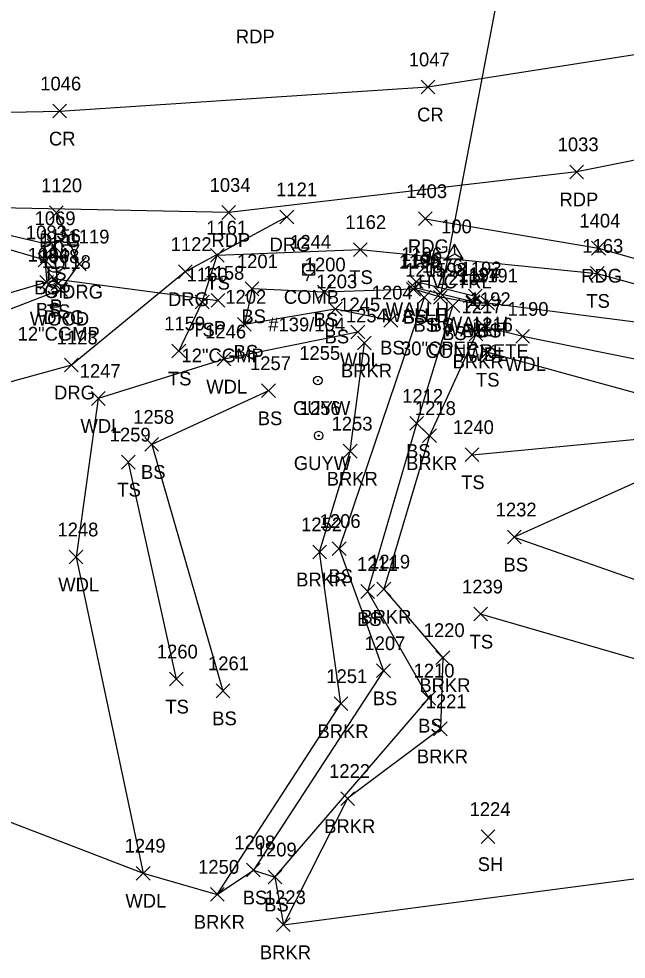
# Model space of a CAD drawing. Extents: x 1633660 to 1636532, y 388643 to 392631.
# Drawn here: x 1633906 to 1633994.3, y 388645.9 to 388782.5 of the extents above; entities that cross this region are included whole.
import ezdxf

# ---------------------------------------------------------------- set-up
doc = ezdxf.new("R2010")
doc.units = 0
for name, color, linetype in [('C_A', 7, 'Continuous'), ('C_I', 7, 'Continuous'), ('CPSM', 7, 'Continuous'), ('D_A', 7, 'Continuous'), ('D_C', 7, 'Continuous'), ('D_I', 7, 'Continuous'), ('D_TIC', 7, 'Continuous'), ('DCP', 7, 'Continuous'), ('DHW', 7, 'Continuous'), ('L_A', 7, 'Continuous'), ('L_I', 7, 'Continuous'), ('L_TIC', 7, 'Continuous'), ('LAWA', 7, 'Continuous'), ('LAWE', 7, 'Continuous'), ('LELB', 7, 'Continuous'), ('LSOGP', 7, 'Continuous'), ('P_A', 7, 'Continuous'), ('P_I', 7, 'Continuous'), ('P_TIC', 7, 'Continuous'), ('PET', 7, 'Continuous'), ('PEU', 7, 'Continuous'), ('PRC', 7, 'Continuous'), ('R_A', 7, 'Continuous'), ('R_C', 7, 'Continuous'), ('R_I', 7, 'Continuous'), ('R_TIC', 7, 'Continuous'), ('RDG', 7, 'Continuous'), ('RGP', 7, 'Continuous'), ('U_A', 7, 'Continuous'), ('U_C', 7, 'Continuous'), ('U_I', 7, 'Continuous'), ('UP', 7, 'Continuous'), ('UPGW', 7, 'Continuous')]:
    doc.layers.add(name, color=color, linetype=linetype)

msp = doc.modelspace()

# ---------------------------------------------------------------- linework, layer by layer
at = {"layer": 'CPSM'}
for p, q in [((1633968.08, 388747.6), (1633969.33, 388749.76)), ((1633970.58, 388747.6), (1633969.33, 388749.76)), ((1633969.34, 388748.32), (1633969.33, 388749.76)), ((1633968.08, 388747.6), (1633969.34, 388748.32)), ((1633969.34, 388748.32), (1633969.34, 388748.32)), ((1633969.34, 388748.32), (1633970.58, 388747.6)), ((1633968.08, 388747.6), (1633970.58, 388747.6))]:
    msp.add_line(p, q, dxfattribs=at)
at = {"layer": 'D_TIC'}
for points in [[(1633910.11, 388743.73), (1633912.11, 388745.73)], [(1633912.11, 388743.73), (1633910.11, 388745.73)], [(1633962.74, 388743.3), (1633964.74, 388745.3)], [(1633964.74, 388743.3), (1633962.74, 388745.3)], [(1633962.54, 388742.42), (1633964.54, 388744.42)], [(1633964.54, 388742.42), (1633962.54, 388744.42)], [(1633933.93, 388740.58), (1633935.93, 388742.58)], [(1633935.93, 388740.58), (1633933.93, 388742.58)], [(1633966.31, 388741.59), (1633968.31, 388743.59)], [(1633968.31, 388741.59), (1633966.31, 388743.59)], [(1633971, 388740.37), (1633973, 388742.37)], [(1633973, 388740.37), (1633971, 388742.37)], [(1633971.33, 388741.21), (1633973.33, 388743.21)], [(1633973.33, 388741.21), (1633971.33, 388743.21)]]:
    msp.add_lwpolyline(points, dxfattribs=at)
at = {"layer": 'DCP'}
for points in [[(1633978.41, 388800.74), (1633967.31, 388742.59)], [(1633911.11, 388744.73), (1633934.93, 388741.58)]]:
    msp.add_lwpolyline(points, dxfattribs=at)
at = {"layer": 'DHW'}
for points in [[(1633972.33, 388742.21), (1633972, 388741.37), (1633963.54, 388743.42), (1633963.74, 388744.3)], [(1633963.74, 388744.3), (1633972.33, 388742.21)]]:
    msp.add_lwpolyline(points, dxfattribs=at)
at = {"layer": 'L_TIC'}
for points in [[(1633910.1, 388748.51), (1633912.1, 388750.51)], [(1633912.1, 388748.51), (1633910.1, 388750.51)], [(1633954.61, 388747.95), (1633956.61, 388749.95)], [(1633956.61, 388747.95), (1633954.61, 388749.95)], [(1633908.78, 388746.45), (1633910.78, 388748.45)], [(1633910.78, 388746.45), (1633908.78, 388748.45)], [(1633933.84, 388747.14), (1633935.84, 388749.14)], [(1633935.84, 388747.14), (1633933.84, 388749.14)], [(1633989.07, 388744.5), (1633991.07, 388746.5)], [(1633991.07, 388744.5), (1633989.07, 388746.5)], [(1633909.04, 388743.21), (1633911.04, 388745.21)], [(1633911.04, 388743.21), (1633909.04, 388745.21)], [(1633910.66, 388743), (1633912.66, 388745)], [(1633912.66, 388743), (1633910.66, 388745)], [(1633938.89, 388742.26), (1633940.89, 388744.26)], [(1633940.89, 388742.26), (1633938.89, 388744.26)], [(1633949.4, 388741.79), (1633951.4, 388743.79)], [(1633951.4, 388741.79), (1633949.4, 388743.79)], [(1633962.35, 388742.2), (1633964.35, 388744.2)], [(1633964.35, 388742.2), (1633962.35, 388744.2)], [(1633963.91, 388741.02), (1633965.91, 388743.02)], [(1633965.91, 388741.02), (1633963.91, 388743.02)], [(1633966.26, 388741.03), (1633968.26, 388743.03)], [(1633968.26, 388741.03), (1633966.26, 388743.03)], [(1633931.64, 388740.33), (1633933.64, 388742.33)], [(1633933.64, 388740.33), (1633931.64, 388742.33)], [(1633950.99, 388739.33), (1633952.99, 388741.33)], [(1633952.99, 388739.33), (1633950.99, 388741.33)], [(1633968.07, 388739.81), (1633970.07, 388741.81)], [(1633970.07, 388739.81), (1633968.07, 388741.81)], [(1633970.98, 388740.19), (1633972.98, 388742.19)], [(1633972.98, 388740.19), (1633970.98, 388742.19)], [(1633973.13, 388740.19), (1633975.13, 388742.19)], [(1633975.13, 388740.19), (1633973.13, 388742.19)], [(1633959.06, 388737.71), (1633961.06, 388739.71)], [(1633961.06, 388737.71), (1633959.06, 388739.71)], [(1633937.77, 388737.1), (1633939.77, 388739.1)], [(1633939.77, 388737.1), (1633937.77, 388739.1)], [(1633972.65, 388736.75), (1633974.65, 388738.75)], [(1633974.65, 388736.75), (1633972.65, 388738.75)], [(1633954.26, 388735.98), (1633956.26, 388737.98)], [(1633956.26, 388735.98), (1633954.26, 388737.98)], [(1633971.45, 388735.7), (1633973.45, 388737.7)], [(1633973.45, 388735.7), (1633971.45, 388737.7)], [(1633978.24, 388735.34), (1633980.24, 388737.34)], [(1633980.24, 388735.34), (1633978.24, 388737.34)], [(1633955.22, 388734.38), (1633957.22, 388736.38)], [(1633957.22, 388734.38), (1633955.22, 388736.38)], [(1633928.25, 388733.22), (1633930.25, 388735.22)], [(1633930.25, 388733.22), (1633928.25, 388735.22)], [(1633973.03, 388733.05), (1633975.03, 388735.05)], [(1633975.03, 388733.05), (1633973.03, 388735.05)], [(1633934.82, 388732.05), (1633936.82, 388734.05)], [(1633936.82, 388732.05), (1633934.82, 388734.05)], [(1633941.28, 388727.45), (1633943.28, 388729.45)], [(1633943.28, 388727.45), (1633941.28, 388729.45)], [(1633916.53, 388726.33), (1633918.53, 388728.33)], [(1633918.53, 388726.33), (1633916.53, 388728.33)], [(1633962.83, 388722.7), (1633964.83, 388724.7)], [(1633964.83, 388722.7), (1633962.83, 388724.7)], [(1633964.68, 388720.92), (1633966.68, 388722.92)], [(1633966.68, 388720.92), (1633964.68, 388722.92)], [(1633924.3, 388719.65), (1633926.3, 388721.65)], [(1633926.3, 388719.65), (1633924.3, 388721.65)], [(1633953.15, 388718.67), (1633955.15, 388720.67)], [(1633955.15, 388718.67), (1633953.15, 388720.67)], [(1633970.87, 388718.16), (1633972.87, 388720.16)], [(1633972.87, 388718.16), (1633970.87, 388720.16)], [(1633920.9, 388717.08), (1633922.9, 388719.08)], [(1633922.9, 388717.08), (1633920.9, 388719.08)], [(1633977, 388706.19), (1633979, 388708.19)], [(1633979, 388706.19), (1633977, 388708.19)], [(1633948.71, 388704.03), (1633950.71, 388706.03)], [(1633950.71, 388704.03), (1633948.71, 388706.03)], [(1633951.55, 388704.52), (1633953.55, 388706.52)], [(1633953.55, 388704.52), (1633951.55, 388706.52)], [(1633913.3, 388703.29), (1633915.3, 388705.29)], [(1633915.3, 388703.29), (1633913.3, 388705.29)], [(1633955.71, 388698.28), (1633957.71, 388700.28)], [(1633957.71, 388698.28), (1633955.71, 388700.28)], [(1633958.04, 388698.62), (1633960.04, 388700.62)], [(1633960.04, 388698.62), (1633958.04, 388700.62)], [(1633972.11, 388695), (1633974.11, 388697)], [(1633974.11, 388695), (1633972.11, 388697)], [(1633966.62, 388688.67), (1633968.62, 388690.67)], [(1633968.62, 388688.67), (1633966.62, 388690.67)], [(1633958, 388686.77), (1633960, 388688.77)], [(1633960, 388686.77), (1633958, 388688.77)], [(1633927.88, 388685.56), (1633929.88, 388687.56)], [(1633929.88, 388685.56), (1633927.88, 388687.56)], [(1633934.66, 388683.85), (1633936.66, 388685.85)], [(1633936.66, 388683.85), (1633934.66, 388685.85)], [(1633951.81, 388681.98), (1633953.81, 388683.98)], [(1633953.81, 388681.98), (1633951.81, 388683.98)], [(1633964.59, 388682.79), (1633966.59, 388684.79)], [(1633966.59, 388682.79), (1633964.59, 388684.79)], [(1633966.26, 388678.33), (1633968.26, 388680.33)], [(1633968.26, 388678.33), (1633966.26, 388680.33)], [(1633952.78, 388668.2), (1633954.78, 388670.2)], [(1633954.78, 388668.2), (1633952.78, 388670.2)], [(1633973.2, 388662.67), (1633975.2, 388664.67)], [(1633975.2, 388662.67), (1633973.2, 388664.67)], [(1633923.06, 388657.35), (1633925.06, 388659.35)], [(1633925.06, 388657.35), (1633923.06, 388659.35)], [(1633939.09, 388657.82), (1633941.09, 388659.82)], [(1633941.09, 388657.82), (1633939.09, 388659.82)], [(1633942.21, 388656.8), (1633944.21, 388658.8)], [(1633944.21, 388656.8), (1633942.21, 388658.8)], [(1633933.83, 388654.28), (1633935.83, 388656.28)], [(1633935.83, 388654.28), (1633933.83, 388656.28)], [(1633943.44, 388649.87), (1633945.44, 388651.87)], [(1633945.44, 388649.87), (1633943.44, 388651.87)]]:
    msp.add_lwpolyline(points, dxfattribs=at)
at = {"layer": 'LAWA'}
for points in [[(1633955.26, 388736.98), (1633935.82, 388733.05), (1633917.53, 388727.33), (1633914.3, 388704.29), (1633924.06, 388658.35)], [(1634213.54, 388715.93), (1634181.29, 388718.06), (1634158.57, 388709.96), (1634132.08, 388702.35), (1634126.3, 388716.32), (1634107.18, 388718.38), (1634087.11, 388719.77), (1634044.14, 388728.03), (1634007.74, 388730.58), (1633979.24, 388736.34), (1633973.65, 388737.75)]]:
    msp.add_lwpolyline(points, dxfattribs=at)
at = {"layer": 'LAWE'}
for points in [[(1633972.45, 388736.7), (1633965.68, 388721.92), (1633959.04, 388699.62), (1633967.62, 388689.67), (1633967.26, 388679.33), (1633953.78, 388669.2), (1633944.44, 388650.87)], [(1633934.83, 388655.28), (1633952.81, 388682.98), (1633949.71, 388705.03), (1633954.15, 388719.67), (1633956.22, 388735.38)]]:
    msp.add_lwpolyline(points, dxfattribs=at)
at = {"layer": 'LELB'}
for points in [[(1633911.66, 388744), (1633911.1, 388749.51), (1633895.3, 388753.2), (1633839.2, 388752.39), (1633786.72, 388748.73), (1633746.63, 388742.98), (1633714.32, 388735.32), (1633689.52, 388727.84)], [(1633690.14, 388726.28), (1633715.09, 388734.26), (1633748.91, 388740.99), (1633779.57, 388746.6), (1633826.21, 388749.36), (1633872.99, 388751.1), (1633902.8, 388749.5), (1633909.78, 388747.45), (1633910.04, 388744.21), (1633875.63, 388734.16), (1633829.55, 388729.69), (1633792.31, 388730.74), (1633761.73, 388730.77), (1633732.76, 388723.1), (1633695, 388705.89)], [(1633929.25, 388734.22), (1633932.64, 388741.33), (1633934.84, 388748.14), (1633955.61, 388748.95), (1633990.07, 388745.5), (1634019.59, 388737.41), (1634056.05, 388731.14), (1634102.32, 388725.85), (1634131.53, 388723.22), (1634169.63, 388722.22), (1634213.51, 388722.74)], [(1634103.78, 388721.69), (1634089.59, 388723.27), (1634044.5, 388730.63), (1634008.78, 388736.74), (1633974.13, 388741.19), (1633971.98, 388741.19), (1633967.26, 388742.03), (1633963.35, 388743.2), (1633950.4, 388742.79), (1633939.89, 388743.26), (1633938.77, 388738.1), (1633951.99, 388740.33), (1633960.06, 388738.71)], [(1633964.91, 388742.02), (1633952.55, 388705.52), (1633959, 388687.77), (1633940.09, 388658.82)], [(1633943.21, 388657.8), (1633965.59, 388683.79), (1633956.71, 388699.28), (1633963.83, 388723.7), (1633969.07, 388740.81)], [(1634025.68, 388725.69), (1633998.33, 388727.39), (1633974.03, 388734.05)], [(1633942.28, 388728.45), (1633925.3, 388720.65), (1633935.66, 388684.85)], [(1634027.27, 388723.64), (1634003.26, 388718.58), (1633978, 388707.19), (1634015.59, 388694.03), (1634040.67, 388699.59), (1634065.09, 388695.5)], [(1633971.87, 388719.16), (1633998.85, 388721.73)], [(1633921.9, 388718.08), (1633928.88, 388686.56)], [(1634057.83, 388688.85), (1634031.65, 388692.09), (1634009.4, 388685.46), (1633973.11, 388696)]]:
    msp.add_lwpolyline(points, dxfattribs=at)
at = {"layer": 'LSOGP'}
msp.add_lwpolyline([(1633892.15, 388670.64), (1633924.06, 388658.35), (1633934.83, 388655.28), (1633940.09, 388658.82), (1633943.21, 388657.8), (1633944.44, 388650.87), (1634007.22, 388659.11), (1634047.38, 388665.25), (1634068.61, 388685.27), (1634091.13, 388687.87), (1634119.65, 388686.04), (1634149.89, 388685.18), (1634208.91, 388690.49), (1634214.85, 388708.43), (1634213.54, 388715.93), (1634213.47, 388720.91), (1634213.51, 388722.74), (1634213.85, 388724.5), (1634214.78, 388736.17), (1634218.98, 388740.85), (1634254.67, 388740.24)], dxfattribs=at)
at = {"layer": 'P_TIC'}
for points in [[(1633964.45, 388771.58), (1633966.45, 388773.58)], [(1633966.45, 388771.58), (1633964.45, 388773.58)], [(1633910.93, 388768.08), (1633912.93, 388770.08)], [(1633912.93, 388768.08), (1633910.93, 388770.08)], [(1633986.08, 388759.24), (1633988.08, 388761.24)], [(1633988.08, 388759.24), (1633986.08, 388761.24)], [(1633935.49, 388753.34), (1633937.49, 388755.34)], [(1633937.49, 388753.34), (1633935.49, 388755.34)], [(1633964.07, 388752.44), (1633966.07, 388754.44)], [(1633966.07, 388752.44), (1633964.07, 388754.44)], [(1633989.25, 388748.16), (1633991.25, 388750.16)], [(1633991.25, 388748.16), (1633989.25, 388750.16)]]:
    msp.add_lwpolyline(points, dxfattribs=at)
at = {"layer": 'PET'}
msp.add_lwpolyline([(1634233.66, 388838.29), (1634176.14, 388816.11), (1634127.42, 388797.4), (1634083.73, 388783.04), (1634035.91, 388770.06), (1633987.08, 388760.24), (1633936.49, 388754.34), (1633886.38, 388755.37), (1633827.16, 388754.09), (1633779.6, 388750.43), (1633734.35, 388742.35), (1633709.35, 388735.6), (1633689.74, 388728.83)], dxfattribs=at)
at = {"layer": 'PEU'}
msp.add_lwpolyline([(1633965.07, 388753.44), (1633990.25, 388749.16), (1634020.6, 388740.58), (1634057, 388733.24), (1634101.12, 388727.81), (1634139.19, 388724.39), (1634181.63, 388724.18), (1634213.85, 388724.5)], dxfattribs=at)
at = {"layer": 'PRC'}
msp.add_lwpolyline([(1633685.21, 388740.89), (1633722.47, 388753.09), (1633765.95, 388761.74), (1633808.84, 388766.45), (1633860.63, 388768.05), (1633911.93, 388769.08), (1633965.45, 388772.58), (1634019.68, 388781.06), (1634071.37, 388793.87), (1634111.14, 388806.36), (1634160.92, 388824.06), (1634207.93, 388842.02), (1634253.71, 388860.36), (1634302.74, 388880.25), (1634347.86, 388899.14), (1634390.05, 388916.89), (1634425.6, 388933.8), (1634443.27, 388943.77), (1634464.46, 388957.57)], dxfattribs=at)
at = {"layer": 'R_TIC'}
for points in [[(1633910.44, 388753.3), (1633912.44, 388755.3)], [(1633912.44, 388753.3), (1633910.44, 388755.3)], [(1633943.95, 388752.7), (1633945.95, 388754.7)], [(1633945.95, 388752.7), (1633943.95, 388754.7)], [(1633913.78, 388745.85), (1633915.78, 388747.85)], [(1633915.78, 388745.85), (1633913.78, 388747.85)], [(1633929.18, 388744.75), (1633931.18, 388746.75)], [(1633931.18, 388744.75), (1633929.18, 388746.75)], [(1633911.07, 388742.14), (1633913.07, 388744.14)], [(1633913.07, 388742.14), (1633911.07, 388744.14)], [(1633912.62, 388731.19), (1633914.62, 388733.19)], [(1633914.62, 388731.19), (1633912.62, 388733.19)]]:
    msp.add_lwpolyline(points, dxfattribs=at)
at = {"layer": 'RDG'}
for points in [[(1633696.84, 388696.34), (1633718.61, 388710.13), (1633753.19, 388721.71), (1633815.96, 388725.01), (1633854.78, 388728.2), (1633888.67, 388734.15), (1633912.07, 388743.14), (1633914.78, 388746.85), (1633911.44, 388754.3)], [(1633944.95, 388753.7), (1633930.18, 388745.75), (1633913.62, 388732.19), (1633871.15, 388720.48), (1633820.72, 388716.51), (1633780.18, 388714.86), (1633742.93, 388709.56), (1633718.39, 388700.15), (1633699.77, 388685.7)]]:
    msp.add_lwpolyline(points, dxfattribs=at)
at = {"layer": 'RGP'}
msp.add_line((1633911.24, 388746.92), (1633911.24, 388746.92), dxfattribs=at)
for radius in [1.25, 0.0833]:
    msp.add_circle((1633911.24, 388746.92), radius, dxfattribs=at)
at = {"layer": 'UP'}
for p, q in [((1633947.29, 388745.24), (1633947.29, 388746.91)), ((1633947.29, 388746.91), (1633948.95, 388746.91)), ((1633948.37, 388747.74), (1633948.12, 388746.91)), ((1633948.95, 388746.91), (1633948.95, 388745.24)), ((1633948.95, 388745.24), (1633947.29, 388745.24)), ((1633947.87, 388744.41), (1633948.12, 388745.24)), ((1633948.12, 388746.08), (1633948.12, 388746.08))]:
    msp.add_line(p, q, dxfattribs=at)
msp.add_circle((1633948.12, 388746.08), 0.833, dxfattribs=at)
at = {"layer": 'UPGW'}
for centre, radius in [((1633949.44, 388729.94), 0.625), ((1633949.44, 388729.94), 0.0833), ((1633949.57, 388721.93), 0.625), ((1633949.57, 388721.93), 0.0833)]:
    msp.add_circle(centre, radius, dxfattribs=at)

# ---------------------------------------------------------------- texts
at = {"layer": 'C_A'}
msp.add_text('HVCTRL', height=2, dxfattribs=at).set_placement((1633964.03, 388743.32))
at = {"layer": 'C_I'}
msp.add_text('100', height=2, dxfattribs=at).set_placement((1633967.37, 388751.32))
at = {"layer": 'D_A'}
for s, p in [('P', (1633910.49, 388739.73)), ('WALLH', (1633959.33, 388739.3)), ('WALLH', (1633959.13, 388738.42)), ('P', (1633934.31, 388736.58)), ('P', (1633966.69, 388737.59)), ('WALLH', (1633967.6, 388736.37)), ('WALLH', (1633967.92, 388737.21))]:
    msp.add_text(s, height=2, dxfattribs=at).set_placement(p)
at = {"layer": 'D_C'}
for s, p in [('12"CGMP', (1633905.81, 388735.73)), ('30"CPEP', (1633961.54, 388733.59)), ('12"CGMP', (1633929.63, 388732.58)), ('CONCRETE', (1633965.09, 388733.21))]:
    msp.add_text(s, height=2, dxfattribs=at).set_placement(p)
at = {"layer": 'D_I'}
for s, p in [('1157', (1633908.98, 388747.73)), ('1196', (1633961.56, 388747.3)), ('1195', (1633961.41, 388746.42)), ('1158', (1633932.81, 388744.58)), ('1376', (1633964.56, 388745.59)), ('1193', (1633970.2, 388745.21)), ('1194', (1633969.88, 388744.37))]:
    msp.add_text(s, height=2, dxfattribs=at).set_placement(p)
at = {"layer": 'L_A'}
for s, p in [('TS', (1633909.51, 388744.51)), ('TS', (1633933.25, 388743.14)), ('TS', (1633954.02, 388743.95)), ('BS', (1633908.23, 388742.45)), ('TS', (1633988.48, 388740.5)), ('BS', (1633908.48, 388739.21)), ('TS', (1633910.07, 388739)), ('BS', (1633938.34, 388738.26)), ('BS', (1633948.84, 388737.79)), ('BS', (1633961.79, 388738.2)), ('TS', (1633931.05, 388736.33)), ('BS', (1633963.35, 388737.02)), ('BS', (1633965.7, 388737.03)), ('BS', (1633950.43, 388735.33)), ('BS', (1633967.51, 388735.81)), ('BS', (1633970.42, 388736.19)), ('BS', (1633972.57, 388736.19)), ('BS', (1633958.5, 388733.71)), ('BS', (1633937.21, 388733.1)), ('WDL', (1633971.07, 388732.75)), ('WDL', (1633952.67, 388731.98)), ('BRKR', (1633969.04, 388731.7)), ('WDL', (1633976.66, 388731.34)), ('BRKR', (1633952.81, 388730.38)), ('TS', (1633927.66, 388729.22)), ('TS', (1633972.44, 388729.05)), ('WDL', (1633933.23, 388728.05)), ('BS', (1633940.72, 388723.45)), ('WDL', (1633914.95, 388722.33)), ('BS', (1633962.27, 388718.7)), ('BRKR', (1633962.28, 388716.92)), ('BS', (1633923.74, 388715.65)), ('BRKR', (1633950.74, 388714.67)), ('TS', (1633920.31, 388713.08)), ('TS', (1633970.28, 388714.16)), ('BS', (1633976.44, 388702.19)), ('BRKR', (1633946.3, 388700.03)), ('BS', (1633950.99, 388700.52)), ('WDL', (1633911.72, 388699.29)), ('BS', (1633955.15, 388694.28)), ('BRKR', (1633955.63, 388694.62)), ('TS', (1633971.52, 388691)), ('BRKR', (1633964.21, 388684.67)), ('BS', (1633957.44, 388682.77)), ('TS', (1633927.29, 388681.56)), ('BS', (1633934.1, 388679.85)), ('BRKR', (1633949.4, 388677.98)), ('BS', (1633964.03, 388678.79)), ('BRKR', (1633963.85, 388674.33)), ('BRKR', (1633950.37, 388664.2)), ('SH', (1633972.69, 388658.67)), ('WDL', (1633921.48, 388653.35)), ('BS', (1633938.53, 388653.82)), ('BS', (1633941.65, 388652.8)), ('BRKR', (1633931.42, 388650.28)), ('BRKR', (1633941.03, 388645.87))]:
    msp.add_text(s, height=2, dxfattribs=at).set_placement(p)
at = {"layer": 'L_I'}
for s, p in [('1069', (1633908.28, 388752.51)), ('1162', (1633953.43, 388751.95)), ('1083', (1633907.01, 388750.45)), ('1161', (1633933.23, 388751.14)), ('1084', (1633907.27, 388747.21)), ('1163', (1633987.9, 388748.5)), ('1068', (1633908.84, 388747)), ('1201', (1633937.69, 388746.26)), ('1199', (1633961.22, 388746.2)), ('1200', (1633947.54, 388745.79)), ('1205', (1633962.14, 388745.02)), ('1198', (1633965.14, 388745.03)), ('1160', (1633930.38, 388744.33)), ('1203', (1633949.22, 388743.33)), ('1213', (1633966.94, 388743.81)), ('1197', (1633969.85, 388744.19)), ('1191', (1633972.57, 388744.19)), ('1204', (1633957.28, 388741.71)), ('1202', (1633936, 388741.1)), ('1192', (1633971.53, 388740.75)), ('1245', (1633952.56, 388739.98)), ('1217', (1633970.33, 388739.7)), ('1190', (1633977.03, 388739.34)), ('1254', (1633953.53, 388738.38)), ('1159', (1633927.12, 388737.22)), ('1216', (1633971.85, 388737.05)), ('1246', (1633933.07, 388736.05)), ('1257', (1633939.59, 388731.45)), ('1247', (1633914.84, 388730.33)), ('1212', (1633961.71, 388726.7)), ('1218', (1633963.56, 388724.92)), ('1258', (1633922.61, 388723.65)), ('1253', (1633951.45, 388722.67)), ('1240', (1633969.09, 388722.16)), ('1259', (1633919.2, 388721.08)), ('1232', (1633975.3, 388710.19)), ('1252', (1633947.02, 388708.03)), ('1206', (1633949.72, 388708.52)), ('1248', (1633911.6, 388707.29)), ('1211', (1633955.15, 388702.28)), ('1219', (1633956.91, 388702.62)), ('1239', (1633970.41, 388699)), ('1220', (1633964.84, 388692.67)), ('1207', (1633956.23, 388690.77)), ('1260', (1633926.05, 388689.56)), ('1261', (1633933.49, 388687.85)), ('1251', (1633950.68, 388685.98)), ('1210', (1633963.37, 388686.79)), ('1221', (1633965.13, 388682.33)), ('1222', (1633951.09, 388672.2)), ('1224', (1633971.51, 388666.67)), ('1249', (1633921.36, 388661.35)), ('1208', (1633937.32, 388661.82)), ('1209', (1633940.43, 388660.8)), ('1250', (1633932.05, 388658.28)), ('1223', (1633941.75, 388653.87))]:
    msp.add_text(s, height=2, dxfattribs=at).set_placement(p)
at = {"layer": 'P_A'}
for s, p in [('RDP', (1633937.54, 388778.92)), ('CR', (1633963.88, 388767.58)), ('CR', (1633910.36, 388764.08)), ('RDP', (1633984.57, 388755.24)), ('RDP', (1633933.98, 388749.34)), ('RDG', (1633962.55, 388748.44)), ('RDG', (1633987.73, 388744.16))]:
    msp.add_text(s, height=2, dxfattribs=at).set_placement(p)
at = {"layer": 'P_I'}
for s, p in [('1047', (1633962.67, 388775.58)), ('1046', (1633909.1, 388772.08)), ('1033', (1633984.31, 388763.24)), ('1034', (1633933.72, 388757.34)), ('1403', (1633962.29, 388756.44)), ('1404', (1633987.47, 388752.16))]:
    msp.add_text(s, height=2, dxfattribs=at).set_placement(p)
at = {"layer": 'R_A'}
for s, p in [('DRG', (1633908.93, 388749.3)), ('DRG', (1633942.44, 388748.7)), ('GP', (1633909.67, 388741.92)), ('DRG', (1633912.27, 388741.85)), ('DRG', (1633927.67, 388740.75)), ('DRG', (1633909.56, 388738.14)), ('DRG', (1633911.11, 388727.19))]:
    msp.add_text(s, height=2, dxfattribs=at).set_placement(p)
at = {"layer": 'R_C'}
msp.add_text('WOOD', height=2, dxfattribs=at).set_placement((1633907.59, 388737.92))
at = {"layer": 'R_I'}
for s, p in [('1120', (1633909.23, 388757.3)), ('1121', (1633943.39, 388756.7)), ('1156', (1633909.05, 388749.92)), ('1119', (1633913.21, 388749.85)), ('1122', (1633928.06, 388748.75)), ('1118', (1633910.51, 388746.14)), ('1123', (1633911.5, 388735.19))]:
    msp.add_text(s, height=2, dxfattribs=at).set_placement(p)
at = {"layer": 'U_A'}
for s, p in [('COMB', (1633944.51, 388741.08)), ('GUYW', (1633945.84, 388724.94)), ('GUYW', (1633945.96, 388716.93))]:
    msp.add_text(s, height=2, dxfattribs=at).set_placement(p)
at = {"layer": 'U_C'}
msp.add_text('#139/104', height=2, dxfattribs=at).set_placement((1633942.25, 388737.08))
at = {"layer": 'U_I'}
for s, p in [('1244', (1633945.43, 388749.08)), ('1255', (1633946.75, 388732.94)), ('1256', (1633946.82, 388724.93))]:
    msp.add_text(s, height=2, dxfattribs=at).set_placement(p)

doc.saveas('drawing.dxf')
